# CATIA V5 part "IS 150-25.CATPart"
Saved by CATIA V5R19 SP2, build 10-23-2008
Part number: BX 150-25
Bounding box of the stored display mesh (mm): x -15.868 to 15.868, y -15.868 to 15.868, z 0 to 100
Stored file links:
  C:\Users\Bora\Desktop\3D Katı model\IS serisi\IS 150\BX 150-25.CATPart
  C:\Program Files\Dassault Systemes\B19\intel_a\reffiles\standard\MetricThickPitch.txt
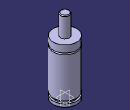
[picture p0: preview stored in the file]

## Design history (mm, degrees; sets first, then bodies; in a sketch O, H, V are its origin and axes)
Body1 (main body)
  Sketch1 on yz-plane, origin (0, 0, 0), H (0, 1, 0), V (0, 0, 1)
    point P3 (6, 99)
    point P5 (6, 99)
    point P7 (16, 63.5)
    point P8 (16, 61.5)
    point P12 (16, 61.5)
    point P13 (16, 63.5)
    line L1 (16, 0) -> (16, 4)
    line L2 (6, 99) -> (6, 73)
    arc A1 centre (5, 99) radius 1 from (6, 99) to (5, 100) ccw
    arc A2 centre (16, 62.5) radius 1 from (16, 63.5) to (16, 61.5) ccw
    line L3 (13.5, 7.5) -> (13.5, 4)
    line L4 (16, 7.5) -> (16, 61.5)
    line L5 (16, 63.5) -> (16, 73)
    line L6 (0, 0) -> (16, 0)
    line L7 (13.5, 4) -> (16, 4)
    line L8 (13.5, 7.5) -> (16, 7.5)
    line L9 (6, 73) -> (16, 73)
    line L10 (5, 100) -> (0, 100)
    point P15 (0, 100)
    horizontal: L6 H, L7 H, L8 H, L9 H
    tangency: L10 A1
    coincidence: P15 V, P3 P5, P7 P13, P8 P12
  Shaft1: profile Sketch1, axis Sketch1.V, angle 360
  Sketch2 on face of Shaft1 from Sketch1.L6, origin (0, 0, 0), H (1, 0, 0), V (0, -1, 0)
    point P1 (0, 0)
  Hole1: placed by Sketch2, at (0, 0, 0) direction (0, 0, 1), diameter 6.647, depth 7, threaded "M8", thread diameter 8, thread depth 7, pitch 1.25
